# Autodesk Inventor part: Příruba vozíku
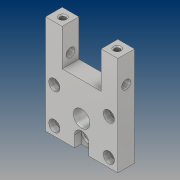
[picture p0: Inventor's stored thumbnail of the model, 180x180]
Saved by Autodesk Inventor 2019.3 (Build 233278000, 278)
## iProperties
Created: 2019-01
Part Number: Příruba vozíku
Material: Hliník 6061-AHC
Document SubType Name: Modeling
Designer: B-hon
Density: 2.7 g/cm^3
Appearance: Hliník – tmavý
Author: B-hon
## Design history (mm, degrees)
sketch "Náčrt1"
  geometry: L1 (-24.5, 16)-(24.5, 16); L2 (24.5, 16)-(24.5, -16); L3 (24.5, -16)-(-24.5, -16); L4 (-24.5, -16)-(-24.5, 16); L5 (-24.5, 16)-(24.5, -16); L6 (24.5, 16)-(-24.5, -16); L7 (32.5, -24)-(-32.5, -24); L8 (-32.5, -24)-(-32.5, 56); L9 (32.5, 56)-(32.5, -24); L10 (-32.5, 56)-(32.5, 56); 1 further point
  constraints: 20 end point, 3 horizontal, 3 parallel, 2 midpoint, 2 perpendicular
  dimensions: "d0" = 49 distance of L2.end L3.end; "d1" = 32 distance of L1.end L2.end; "d4" = 80 distance between parallel lines of L7 L10; "d21" = 8 distance between parallel lines of L9 L2; "d22" = 8 distance between parallel lines of L4 L8; "d23" = 8 distance between parallel lines of L7 L3
extrude "Vysunutí1" new body sketch "Náčrt1" distance "d5" = 12; taper "d6" = 0 deg
sketch "Náčrt2"
  geometry: L1 (0, 80)-(0, 0) reference; L2 (0, 0)-(-12, 0) reference; 2 further points
  dimensions: "d7" = 4.5 distance from line of L1 point (-4.5, 65); "d8" = 65 distance from line of L2 point (-4.5, 65)
hole "Díra1" sketch "Náčrt2" at (-4.5, 65) diameter "d9" = 8; stored, may be unused: countersink angle "d13" = 90 deg, drill point angle "d15" = 118 deg; dims "d10" = 6, "d11" = 4, "d12" = 2, "d14" = 8
sketch "Náčrt3"
  geometry: L1 (32.5, 56)-(-32.5, 56) reference; L2 (-17.5, 56)-(17.5, 56); L3 (17.5, 56)-(17.5, 32); L4 (17.5, 32)-(-17.5, 32); L5 (-17.5, 32)-(-17.5, 56); L6 (-32.5, -24)-(32.5, -24) reference; 1 further point
  constraints: 8 end point, 2 parallel, 1 horizontal, 1 perpendicular, 1 point on line
  dimensions: "d16" = 56 distance between parallel lines of L4 L6; "d17" = 35 distance of L3.end L4.end; "d18" = 15 distance from line of L1.end L5
extrude "Vysunutí2" cut sketch "Náčrt3" distance "d19" = 12; taper "d20" = 0 deg
sketch "Náčrt5"
  geometry: L1 (-24.5, 16)-(24.5, 16); L2 (24.5, 16)-(24.5, -16); L3 (24.5, -16)-(-24.5, -16); L4 (-24.5, -16)-(-24.5, 16); L5 (-24.5, 16)-(24.5, -16); L6 (24.5, 16)-(-24.5, -16); 5 further points
  constraints: 12 end point, 4 coincident, 2 midpoint, 2 parallel, 1 horizontal, 1 perpendicular
  dimensions: "d24" = 49 distance of L2.end L3.end; "d25" = 32 distance of L1.end L2.end
hole "Díra2" sketch "Náčrt5" at (-24.5, 16), (24.5, 16), (24.5, -16), (-24.5, -16) diameter "d26" = 5.3; stored, may be unused: countersink angle "d30" = 90 deg, drill point angle "d32" = 118 deg; dims "d27" = 6, "d28" = 10, "d29" = 5.7, "d31" = 8
node "Upravit přímo1"
sketch "Náčrt6"
  geometry: L1 (-32.5, -24)-(32.5, -24) reference; C1 r 6.5 at (0, -14); 1 further point
  constraints: 1 centre point
  dimensions: "d36" = 13 diameter of C1; "d37" = 10 distance from line of L1 C1.centre
extrude "Vysunutí3" cut sketch "Náčrt6" distance "d38" = 8; taper "d39" = 0 deg
sketch "Náčrt7"
  geometry: L1 (6.5, -48.468)-(-6.5, -48.468); L2 (-6.5, -48.468)-(-6.5, -14); L3 (-6.5, -14)-(6.5, -14); L4 (6.5, -14)-(6.5, -48.468); L5 (6.5, -48.468)-(-6.5, -14); L6 (-6.5, -48.468)-(6.5, -14); 3 further points
  constraints: 12 end point, 2 midpoint, 2 parallel, 1 horizontal, 1 horizontal alignment, 1 perpendicular, 1 other
  dimensions: "d40" = 13 distance of L2.end L3.end
extrude "Vysunutí4" cut sketch "Náčrt7" distance "d41" = 6; taper "d42" = 0 deg
node "Upravit přímo2"
sketch "Náčrt8"
  geometry: L1 (-32.5, -24)-(-6.5, -24) reference; L2 (-32.5, 65)-(-32.5, -24) reference; 2 further points
  dimensions: "d46" = 26 distance from line of L1 point (0, 2); "d47" = 32.5 distance from line of L2 point (0, 2)
hole "Díra3" sketch "Náčrt8" at (0, 2) diameter "d48" = 15; stored, may be unused: countersink angle "d52" = 90 deg, drill point angle "d54" = 118 deg; dims "d49" = 6, "d50" = 4, "d51" = 2, "d53" = 13
sketch "Náčrt10"
  geometry: L1 (15, 0)-(0, 0) reference; L2 (15, 0)-(15, 15) reference; L3 (65, 15)-(65, 0) reference; L4 (50, 15)-(65, 15) reference; 3 further points
  dimensions: "d64" = 7.5 distance from line of L1 point (8, 7.5); "d65" = 7 distance from line of L2 point (8, 7.5); "d66" = 8 distance from line of L3 point (57, 7.5); "d67" = 7.5 distance from line of L4 point (57, 7.5)
hole "Díra5" sketch "Náčrt10" at (8, 7.5), (57, 7.5) diameter "d68" = 4.917; stored, may be unused: countersink angle "d72" = 90 deg, drill point angle "d74" = 118 deg; dims "d69" = 12, "d70" = 7, "d71" = 2, "d73" = 17.1
sketch "Náčrt11"
  geometry: C1 r 4 at (-7.5, 65) reference; 2 further points
  constraints: 1 coincident
hole "Díra6" sketch "Náčrt11" at (-7.5, 65) diameter "d75" = 12.5; stored, may be unused: countersink angle "d79" = 90 deg, drill point angle "d81" = 0 deg; dims "d76" = 6, "d77" = 4, "d78" = 2, "d80" = 3
node "Těleso1"
feature "Posunout1" dims "d35" = 9
feature "Posunout2" dims "d45" = 3
other parameters: "d33" = 0, "d34" = 0, "d43" = 0, "d44" = 0
